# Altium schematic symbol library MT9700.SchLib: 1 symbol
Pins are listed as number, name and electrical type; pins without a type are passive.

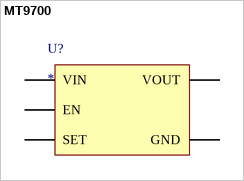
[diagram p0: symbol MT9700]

## MT9700
designator U?
80mΩ, Adjustable Fast Response Current-Limited Power-Distribution Switch; MF: Analog Devices; MP: LT1784CS5#TR
footprint TSOT-23_S5
pins: 1 VOUT, 2 GND, 3 SET, 4 EN, 5 VIN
